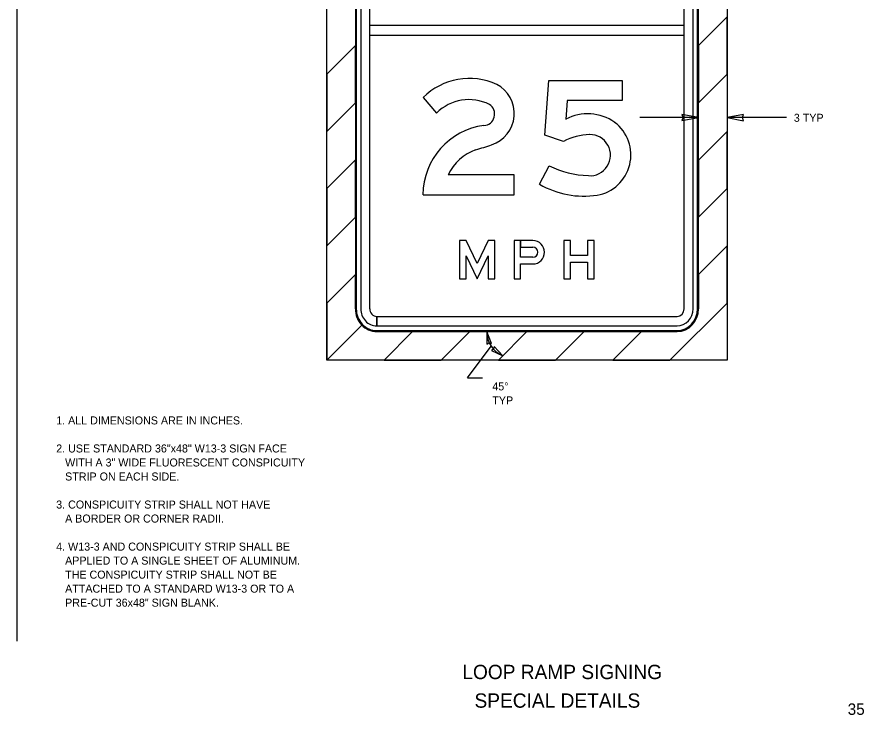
# Model space of a CAD drawing. Extents: x 582908 to 586040, y 1530940 to 1533040.
# Drawn here: x 584558 to 586040, y 1530991 to 1532211 of the extents above; entities that cross this region are included whole.
import ezdxf

# ---------------------------------------------------------------- set-up
doc = ezdxf.new("R2010")
doc.units = 0
for name, color, linetype in [('GSDims', 7, 'Continuous'), ('SheetLinesMisc2_dp', 7, 'Continuous'), ('SignPanel', 7, 'Continuous'), ('TextMisc', 7, 'Continuous'), ('TextNotes', 7, 'Continuous'), ('TextShtNo', 7, 'Continuous')]:
    doc.layers.add(name, color=color, linetype=linetype)

msp = doc.modelspace()

# ---------------------------------------------------------------- linework, layer by layer
at = {"layer": 'GSDims'}
for p, q in [((585750.1, 1532034.7), (585647.3, 1532034.7)), ((585750.1, 1532034.7), (585721.1, 1532040.3)), ((585721.1, 1532040.3), (585723.3, 1532034.7)), ((585723.3, 1532034.7), (585721.1, 1532029.3)), ((585721.1, 1532029.3), (585750.1, 1532034.7)), ((585829.1, 1532040.1), (585800.1, 1532034.7)), ((585904.1, 1532034.7), (585800.1, 1532034.7)), ((585800.1, 1532034.7), (585829.1, 1532029.1)), ((585826.9, 1532034.7), (585829.1, 1532040.1)), ((585829.1, 1532029.1), (585826.9, 1532034.7)), ((585380, 1531660.7), (585379.8, 1531638.5)), ((585387.9, 1531640), (585380, 1531660.7)), ((585346, 1531579.8), (585387.6, 1531635.3)), ((585379.8, 1531638.5), (585383.6, 1531640.9)), ((585383.6, 1531640.9), (585387.9, 1531640)), ((585391.6, 1531630.2), (585387.9, 1531627.9)), ((585392.7, 1531634.6), (585391.6, 1531630.2)), ((585407.9, 1531618.5), (585392.7, 1531634.6)), ((585387.9, 1531627.9), (585407.9, 1531618.5)), ((585346, 1531579.8), (585372.4, 1531579.8))]:
    msp.add_line(p, q, dxfattribs=at)
msp.add_arc((585424.4, 1531659.8), 44.2, 178.9271, 248.409, dxfattribs=at)
at = {"layer": 'SheetLinesMisc2_dp'}
msp.add_line((584558.3, 1533039.8), (584558.3, 1531119.8), dxfattribs=at)
at = {"layer": 'SignPanel'}
for p, q in [((585150.1, 1532420.5), (585150.1, 1531700.6)), ((585150.1, 1532420.5), (585150.1, 1531700.6)), ((585151.6, 1532420.5), (585151.6, 1531700.6)), ((585159.5, 1532420.5), (585159.5, 1531700.6)), ((585175.1, 1532420.5), (585175.1, 1531700.6)), ((585725.1, 1531700.6), (585725.1, 1532420.5)), ((585740.7, 1531700.6), (585740.7, 1532420.5)), ((585748.5, 1531700.6), (585748.5, 1532420.5)), ((585750.1, 1531700.6), (585750.1, 1532420.5)), ((585725.1, 1532195.5), (585175.1, 1532195.5)), ((585175.1, 1532195.5), (585175.1, 1532178.9)), ((585725.1, 1532195.5), (585175.1, 1532195.5)), ((585175.1, 1532195.5), (585175.1, 1532178.9)), ((585725.1, 1532195.5), (585175.1, 1532195.5)), ((585175.1, 1532195.5), (585175.1, 1532178.9)), ((585725.1, 1532178.9), (585725.1, 1532195.5)), ((585725.1, 1532178.9), (585725.1, 1532195.5)), ((585725.1, 1532178.9), (585725.1, 1532195.5)), ((585175.1, 1532178.9), (585725.1, 1532178.9)), ((585175.1, 1532178.9), (585725.1, 1532178.9)), ((585175.1, 1532178.9), (585725.1, 1532178.9)), ((585268.4, 1532069.9), (585292.1, 1532042.6)), ((585268.4, 1532069.9), (585292.1, 1532042.6)), ((585268.4, 1532069.9), (585292.1, 1532042.6)), ((585518.1, 1532031.6), (585518.1, 1532031.6)), ((585472.2, 1531918.1), (585489.1, 1531950.4)), ((585472.2, 1531918.1), (585489.1, 1531950.4)), ((585472.2, 1531918.1), (585489.1, 1531950.4)), ((585489.1, 1531950.4), (585489.1, 1531950.4)), ((585489.1, 1531950.4), (585489.1, 1531950.4)), ((585460.7, 1531790.6), (585439.1, 1531790.6)), ((585439.1, 1531778.9), (585460.7, 1531778.9)), ((585151.7, 1531700.6), (585151.6, 1531700.6)), ((585748.5, 1531700.6), (585748.5, 1531700.6)), ((585187.6, 1531670.6), (585187.6, 1531687.3)), ((585187.7, 1531687.3), (585712.6, 1531687.3)), ((585187.7, 1531687.3), (585187.7, 1531670.6)), ((585187.6, 1531660.6), (585187.6, 1531662.3)), ((585187.6, 1531662.3), (585187.6, 1531662.3)), ((585187.6, 1531662.3), (585712.6, 1531662.3)), ((585187.6, 1531662.3), (585187.6, 1531660.6)), ((585187.6, 1531660.6), (585712.6, 1531660.6)), ((585187.7, 1531670.6), (585712.6, 1531670.6)), ((585712.6, 1531662.3), (585712.6, 1531662.3))]:
    msp.add_line(p, q, dxfattribs=at)
for points in [[(585100.1, 1532510.5), (585800.1, 1532510.5), (585800.1, 1531610.6), (585100.1, 1531610.6)], [(585343.9, 1531793.2), (585363.1, 1531753.1), (585382.3, 1531793.2), (585382.3, 1531753.1), (585393.8, 1531753.1), (585393.8, 1531819.7), (585382.2, 1531819.7), (585363.1, 1531779.8), (585344, 1531819.7), (585332.4, 1531819.7), (585332.4, 1531753.1), (585343.9, 1531753.1)], [(585343.9, 1531793.2), (585363.1, 1531753.1), (585382.3, 1531793.2), (585382.3, 1531753.1), (585393.8, 1531753.1), (585393.8, 1531819.7), (585382.2, 1531819.7), (585363.1, 1531779.8), (585344, 1531819.7), (585332.4, 1531819.7), (585332.4, 1531753.1), (585343.9, 1531753.1)], [(585343.9, 1531793.2), (585363.1, 1531753.1), (585382.3, 1531793.2), (585382.3, 1531753.1), (585393.8, 1531753.1), (585393.8, 1531819.7), (585382.2, 1531819.7), (585363.1, 1531779.8), (585344, 1531819.7), (585332.4, 1531819.7), (585332.4, 1531753.1), (585343.9, 1531753.1)], [(585556.3, 1531793.7), (585526.1, 1531793.7), (585526.1, 1531819.7), (585514.6, 1531819.7), (585514.6, 1531753.1), (585526.1, 1531753.1), (585526.1, 1531782), (585556.3, 1531782), (585556.3, 1531753.1), (585567.8, 1531753.1), (585567.8, 1531819.7), (585556.3, 1531819.7)], [(585556.3, 1531793.7), (585526.1, 1531793.7), (585526.1, 1531819.7), (585514.6, 1531819.7), (585514.6, 1531753.1), (585526.1, 1531753.1), (585526.1, 1531782), (585556.3, 1531782), (585556.3, 1531753.1), (585567.8, 1531753.1), (585567.8, 1531819.7), (585556.3, 1531819.7)], [(585556.3, 1531793.7), (585526.1, 1531793.7), (585526.1, 1531819.7), (585514.6, 1531819.7), (585514.6, 1531753.1), (585526.1, 1531753.1), (585526.1, 1531782), (585556.3, 1531782), (585556.3, 1531753.1), (585567.8, 1531753.1), (585567.8, 1531819.7), (585556.3, 1531819.7)]]:
    msp.add_lwpolyline(points, close=True, dxfattribs=at)
for points in [[(585750.1, 1532060.5), (585800.1, 1532110.5), (585800.1, 1532210.5), (585750.1, 1532160.5), (585750.1, 1532060.5)], [(585150.1, 1532060.6), (585150.1, 1532160.6), (585100.1, 1532110.6), (585100.1, 1532010.6), (585150.1, 1532060.6)], [(585514, 1531992.9), (585481.5, 1532003.8), (585488.6, 1532099.7), (585616.9, 1532099.7), (585616.9, 1532064.7), (585520.6, 1532064.7), (585518.1, 1532031.6)], [(585514, 1531992.9), (585481.5, 1532003.8), (585488.6, 1532099.7), (585616.9, 1532099.7), (585616.9, 1532064.7), (585520.6, 1532064.7), (585518.1, 1532031.6)], [(585514, 1531992.9), (585481.5, 1532003.8), (585488.6, 1532099.7), (585616.9, 1532099.7), (585616.9, 1532064.7), (585520.6, 1532064.7), (585518.1, 1532031.6)], [(585750.1, 1531860.5), (585800.1, 1531910.5), (585800.1, 1532010.5), (585750.1, 1531960.5), (585750.1, 1531860.5)], [(585150.1, 1531860.6), (585150.1, 1531960.6), (585100.1, 1531910.6), (585100.1, 1531810.6), (585150.1, 1531860.6)], [(585268.4, 1531899.7), (585427.9, 1531899.7), (585427.9, 1531934.7), (585312.6, 1531934.7)], [(585268.4, 1531899.7), (585427.9, 1531899.7), (585427.9, 1531934.7), (585312.6, 1531934.7)], [(585268.4, 1531899.7), (585427.9, 1531899.7), (585427.9, 1531934.7), (585312.6, 1531934.7)], [(585460.7, 1531819.7), (585427.6, 1531819.7), (585427.6, 1531753.1), (585439.1, 1531753.1), (585439.1, 1531778.9)], [(585439.1, 1531819.7), (585427.6, 1531819.7), (585427.6, 1531753.1), (585439.1, 1531753.1), (585439.1, 1531778.9), (585460.7, 1531778.9)], [(585439.1, 1531819.7), (585427.6, 1531819.7), (585427.6, 1531753.1), (585439.1, 1531753.1), (585439.1, 1531778.9), (585460.7, 1531778.9)], [(585460.7, 1531819.7), (585439.1, 1531819.7), (585439.1, 1531808.1), (585460.7, 1531808.1)], [(585460.7, 1531790.6), (585439.1, 1531790.6), (585439.1, 1531819.7)], [(585460.7, 1531819.7), (585439.1, 1531819.7), (585439.1, 1531808.1), (585460.7, 1531808.1)], [(585460.7, 1531790.6), (585439.1, 1531790.6), (585439.1, 1531819.7)], [(585439.1, 1531790.6), (585439.1, 1531808.1), (585460.7, 1531808.1)], [(585712.6, 1531660.6), (585650.2, 1531660.6), (585600.2, 1531610.6), (585700.2, 1531610.6), (585800.1, 1531710.5), (585800.1, 1531810.5), (585750.1, 1531760.5)], [(585150.1, 1531700.6), (585150.1, 1531760.6), (585100.1, 1531710.6), (585100.1, 1531610.6), (585161.5, 1531671.9)], [(585750.1, 1531760.5), (585750.1, 1531700.6)], [(585300.2, 1531610.6), (585350.2, 1531660.6), (585250.2, 1531660.6), (585200.2, 1531610.6), (585300.2, 1531610.6)], [(585500.2, 1531610.6), (585550.2, 1531660.6), (585450.2, 1531660.6), (585400.2, 1531610.6), (585500.2, 1531610.6)]]:
    msp.add_lwpolyline(points, dxfattribs=at)
for centre, major_axis, ratio, start_param, end_param in [((585349.5, 1531984.2), (0, 118.8), 0.985, 5.861869, 7.048709), ((585349.5, 1531984.2), (0, 118.8), 0.985, 5.861869, 7.048709), ((585349.5, 1531984.2), (0, 118.8), 0.985, 5.861869, 7.048709), ((585371.6, 1532041.8), (0, 57.2), 0.985, 3.445077, 5.80948), ((585371.6, 1532041.8), (0, 57.2), 0.985, 3.445077, 5.80948), ((585371.6, 1532041.8), (0, 57.2), 0.985, 3.445077, 5.80948), ((585349, 1531983), (0, 83), 0.985, 5.833638, 7.052577), ((585349, 1531983), (0, 83), 0.985, 5.833638, 7.052577), ((585349, 1531983), (0, 83), 0.985, 5.833638, 7.052577), ((585373.8, 1532040.8), (0, 20.1), 0.985, 3.193411, 5.709913), ((585373.8, 1532040.8), (0, 20.1), 0.985, 3.193411, 5.709913), ((585373.8, 1532040.8), (0, 20.1), 0.985, 3.193411, 5.709913), ((585556.5, 1531957.7), (0, 83.6), 0.985, 5.674797, 6.76791), ((585556.5, 1531957.7), (0, 83.6), 0.985, 5.674797, 6.76791), ((585556.5, 1531957.7), (0, 83.6), 0.985, 5.674797, 6.76791), ((585389.5, 1531898.7), (0, 123), 0.985, 0.121378, 1.562513), ((585389.5, 1531898.7), (0, 123), 0.985, 0.121378, 1.562513), ((585389.5, 1531898.7), (0, 123), 0.985, 0.121378, 1.562513), ((585562, 1531969.3), (0, 70.9), 0.985, 3.29706, 5.646286), ((585562, 1531969.3), (0, 70.9), 0.985, 3.29706, 5.646286), ((585562, 1531969.3), (0, 70.9), 0.985, 3.29706, 5.646286), ((585562.1, 1531899.7), (0, 105.2), 0.985, 0.021733, 0.482857), ((585562.1, 1531899.7), (0, 105.2), 0.985, 0.021733, 0.482857), ((585562.1, 1531899.7), (0, 105.2), 0.985, 0.021733, 0.482857), ((585560.8, 1531969), (0, 35.9), 0.985, 3.050128, 6.31212), ((585560.8, 1531969), (0, 35.9), 0.985, 3.050128, 6.31212), ((585560.8, 1531969), (0, 35.9), 0.985, 3.050128, 6.31212), ((585179.7, 1532612.1), (0, 659.8), 0.985, 3.423454, 3.46857), ((585179.7, 1532612.1), (0, 659.8), 0.985, 3.423454, 3.46857), ((585179.7, 1532612.1), (0, 659.8), 0.985, 3.423454, 3.46857), ((585391.2, 1531894.7), (0, 89.3), 0.985, 0.357174, 1.105945), ((585391.2, 1531894.7), (0, 89.3), 0.985, 0.357174, 1.105945), ((585391.2, 1531894.7), (0, 89.3), 0.985, 0.357174, 1.105945), ((585564.8, 1532112.6), (0, 179.5), 0.985, 2.699218, 3.100889), ((585564.8, 1532112.6), (0, 179.5), 0.985, 2.699218, 3.100889), ((585564.8, 1532112.6), (0, 179.5), 0.985, 2.699218, 3.100889), ((585549.4, 1532056.2), (0, 158.8), 0.985, 2.625811, 3.292278), ((585549.4, 1532056.2), (0, 158.8), 0.985, 2.625811, 3.292278), ((585549.4, 1532056.2), (0, 158.8), 0.985, 2.625811, 3.292278), ((585460.7, 1531799.3), (0, 20.4), 0.985, 3.141593, 6.283185), ((585460.7, 1531799.3), (0, 20.4), 0.985, 3.141593, 6.283185), ((585460.7, 1531799.3), (0, 20.4), 0.985, 3.141593, 6.283185), ((585460.7, 1531799.3), (0, 8.75), 0.985, 3.141593, 6.283185), ((585460.7, 1531799.3), (0, 8.75), 0.985, 3.141593, 6.283185), ((585460.7, 1531799.3), (0, 8.75), 0.985, 3.141593, 6.283185), ((585187.6, 1531700.6), (0, 40), 0.937555, 1.570796, 2.370551), ((585187.6, 1531700.6), (0, 40), 0.937555, 1.570796, 3.141593), ((585187.6, 1531700.6), (0, 38.3), 0.937555, 1.570796, 3.141593), ((585187.6, 1531700.6), (0, 30), 0.937555, 1.570796, 3.141593), ((585187.6, 1531700.6), (0, 13.3), 0.937555, 1.570796, 3.141593), ((585712.6, 1531700.6), (0, 40), 0.937555, 3.141593, 4.712389), ((585712.6, 1531700.6), (0, 40), 0.937555, 3.141593, 4.712389), ((585712.6, 1531700.6), (0, 30), 0.937555, 3.141593, 4.712389), ((585712.6, 1531700.6), (0, 13.3), 0.937555, 3.141593, 4.712389), ((585712.6, 1531700.6), (0, 40), 0.937555, 3.141593, 4.712389), ((585712.6, 1531700.6), (0, 38.3), 0.937555, 3.141593, 4.712389)]:
    msp.add_ellipse(centre, major_axis=major_axis, ratio=ratio, start_param=start_param, end_param=end_param, dxfattribs=at)

# ---------------------------------------------------------------- texts
at = {"layer": 'GSDims'}
for s, p in [('3 TYP', (585916.8, 1532027.3)), ('45°', (585389.6, 1531557.9)), ('TYP', (585389.6, 1531533.4))]:
    msp.add_text(s, height=14, dxfattribs=at).set_placement(p)
at = {"layer": 'TextMisc'}
for s, p in [('   LOOP RAMP SIGNING    ', (585309.3, 1531053.3)), ('    SPECIAL DETAILS     ', (585321.3, 1531003.3))]:
    msp.add_text(s, height=25, rotation=360, dxfattribs=at).set_placement(p)
at = {"layer": 'TextNotes'}
for s, p in [('1. ALL DIMENSIONS ARE IN INCHES.', (584627, 1531498.4)), ('2. USE STANDARD 36"x48" W13-3 SIGN FACE', (584627, 1531449.4)), ('   WITH A 3" WIDE FLUORESCENT CONSPICUITY ', (584627, 1531424.9)), ('   STRIP ON EACH SIDE. ', (584627, 1531400.4)), ('3. CONSPICUITY STRIP SHALL NOT HAVE', (584627, 1531351.4)), ('   A BORDER OR CORNER RADII.', (584627, 1531326.9)), ('4. W13-3 AND CONSPICUITY STRIP SHALL BE', (584627, 1531277.9)), ('   APPLIED TO A SINGLE SHEET OF ALUMINUM.', (584627, 1531253.4)), ('   THE CONSPICUITY STRIP SHALL NOT BE ', (584627, 1531228.9)), ('   ATTACHED TO A STANDARD W13-3 OR TO A', (584627, 1531204.4)), ('   PRE-CUT 36x48" SIGN BLANK.', (584627, 1531179.9))]:
    msp.add_text(s, height=14, dxfattribs=at).set_placement(p)
at = {"layer": 'TextShtNo'}
msp.add_text('35', height=20, rotation=360, dxfattribs=at).set_placement((586011, 1530990.8))

doc.saveas('drawing.dxf')
